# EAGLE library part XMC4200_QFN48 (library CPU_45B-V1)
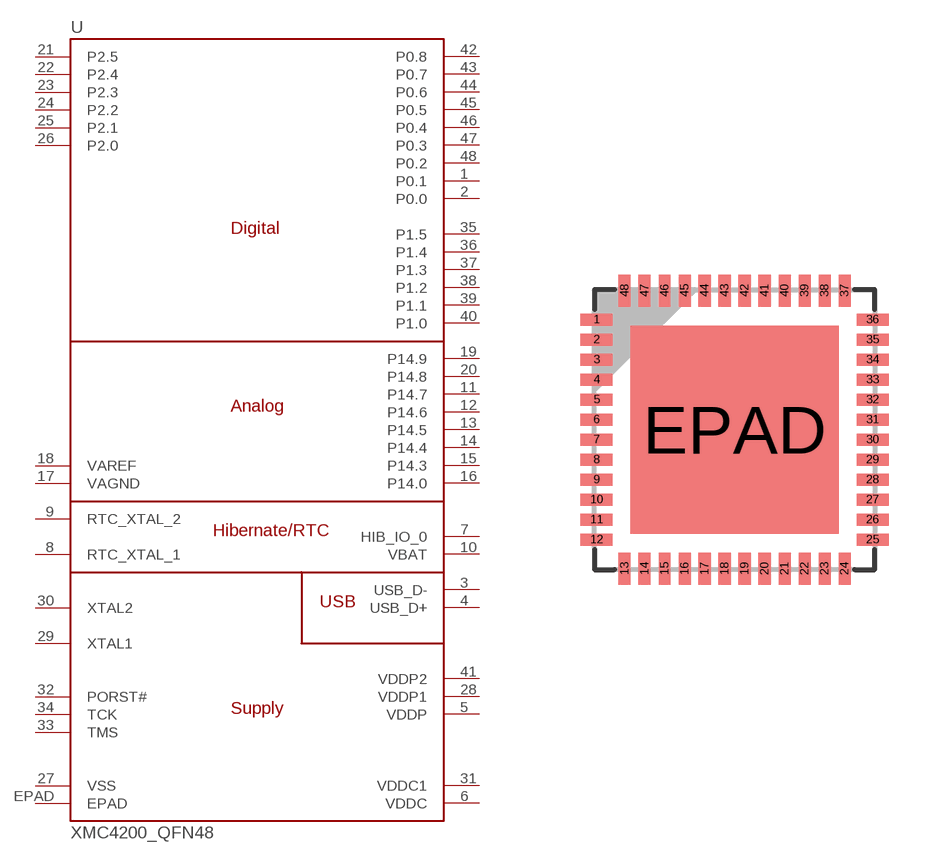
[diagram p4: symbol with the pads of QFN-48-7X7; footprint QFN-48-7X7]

Designator prefix U

## XMC4200_QFN48  [QFN-48-7X7]
1  P0.1
2  P0.0
3  USB_D-
4  USB_D+
5  VDDP
6  VDDC
7  HIB_IO_0
8  RTC_XTAL_1
9  RTC_XTAL_2
10  VBAT
11  P14.7
12  P14.6
13  P14.5
14  P14.4
15  P14.3
16  P14.0
17  VAGND
18  VAREF
19  P14.9
20  P14.8
21  P2.5
22  P2.4
23  P2.3
24  P2.2
25  P2.1
26  P2.0
27  VSS
28  VDDP1
29  XTAL1
30  XTAL2
31  VDDC1
32  PORST#
33  TMS
34  TCK
35  P1.5
36  P1.4
37  P1.3
38  P1.2
39  P1.1
40  P1.0
41  VDDP2
42  P0.8
43  P0.7
44  P0.6
45  P0.5
46  P0.4
47  P0.3
48  P0.2
EPAD  EPAD

## Footprint QFN-48-7X7 (pad centres in mm)
QFN-48 (7x7) Source:
smd 0.8 x 0.3: 1 -3.45,2.75; 2 -3.45,2.25; 3 -3.45,1.75; 4 -3.45,1.25; 5 -3.45,0.75; 6 -3.45,0.25; 7 -3.45,-0.25; 8 -3.45,-0.75; 9 -3.45,-1.25; 10 -3.45,-1.75; 11 -3.45,-2.25; 12 -3.45,-2.75; 25 3.45,-2.75; 26 3.45,-2.25; 27 3.45,-1.75; 28 3.45,-1.25; 29 3.45,-0.75; 30 3.45,-0.25; 31 3.45,0.25; 32 3.45,0.75; 33 3.45,1.25; 34 3.45,1.75; 35 3.45,2.25; 36 3.45,2.75
smd 0.3 x 0.8: 13 -2.75,-3.475; 14 -2.25,-3.475; 15 -1.75,-3.475; 16 -1.25,-3.475; 17 -0.75,-3.475; 18 -0.25,-3.475; 19 0.25,-3.475; 20 0.75,-3.475; 21 1.25,-3.475; 22 1.75,-3.475; 23 2.25,-3.475; 24 2.75,-3.475; 37 2.75,3.475; 38 2.25,3.475; 39 1.75,3.475; 40 1.25,3.475; 41 0.75,3.475; 42 0.25,3.475; 43 -0.25,3.475; 44 -0.75,3.475; 45 -1.25,3.475; 46 -1.75,3.475; 47 -2.25,3.475; 48 -2.75,3.475
smd 5.2 x 5.2: EPAD 0,0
